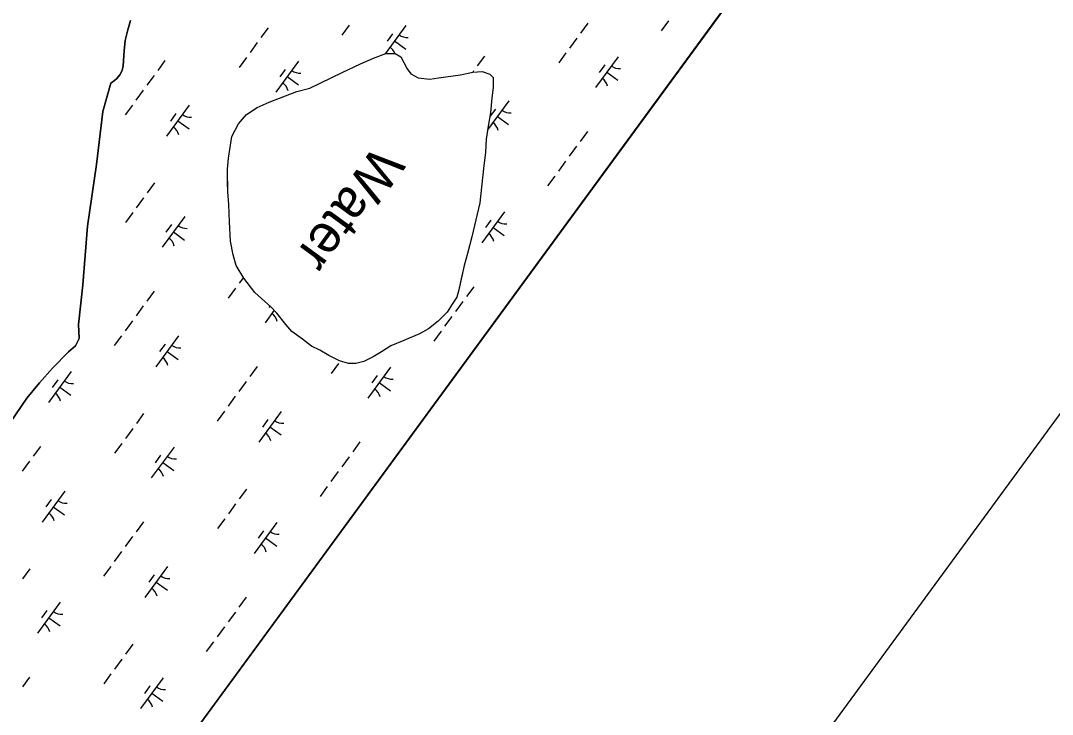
# Model space of a CAD drawing. Extents: x 3905714 to 3926767, y 183354 to 205755.
# Drawn here: x 3915741 to 3917087, y 185637 to 186542 of the extents above; entities that cross this region are included whole.
import ezdxf

# ---------------------------------------------------------------- set-up
doc = ezdxf.new("R2010")
doc.units = 0
for name, color, linetype in [('V-ANNO-SYMB', 7, 'Continuous'), ('V-GRID-FRAM', 7, 'Continuous'), ('V-RIVR-IDEN', 7, 'Continuous'), ('V-TOPO-SHOR', 7, 'Continuous'), ('V-WETL-SWMP', 7, 'Continuous')]:
    doc.layers.add(name, color=color, linetype=linetype)

msp = doc.modelspace()

# ---------------------------------------------------------------- linework, layer by layer
at = {"layer": 'V-ANNO-SYMB'}
msp.add_lwpolyline([(3916223.9, 204226), (3906447.8, 190882.4), (3915690.8, 184110.5), (3925467, 197454.1), (3916223.9, 204226)], dxfattribs=at)
at = {"layer": 'V-GRID-FRAM'}
msp.add_lwpolyline([(3924287.8, 196971.1), (3915521.4, 185005.6), (3909313.3, 189695.8), (3918205.9, 201877.9), (3924287.8, 196971.1)], dxfattribs=at)
at = {"layer": 'V-TOPO-SHOR'}
for points in [[(3915858.8, 186460.7), (3915863.5, 186464), (3915866.8, 186466.7), (3915870.8, 186471.3), (3915873.7, 186477.2), (3915875.2, 186483.1), (3915875.8, 186496), (3915876.3, 186502.8), (3915877.7, 186516), (3915881, 186530.3), (3915884.7, 186542.3)], [(3916261.4, 186133.8), (3916240.8, 186125.2), (3916224, 186118), (3916211.8, 186110.1), (3916200.8, 186103.5), (3916188.6, 186097.6), (3916178.3, 186094.9), (3916168.6, 186094.8), (3916156.9, 186098.6), (3916143.2, 186105.6), (3916131.5, 186112.6), (3916120.5, 186117.7), (3916108.8, 186126.7), (3916095.1, 186136.9), (3916087.2, 186145.9), (3916075.4, 186160.7), (3916067.6, 186169), (3916055.2, 186179.9), (3916046.7, 186187.6), (3916032.3, 186206.2), (3916022.5, 186223), (3916018.5, 186236.5), (3916015.1, 186254.6), (3916013.6, 186279.9), (3916012.7, 186302.5), (3916011.3, 186318.7), (3916011.2, 186331), (3916011, 186348.4), (3916012.2, 186362.7), (3916016.5, 186391.2), (3916025.4, 186407.4), (3916035.6, 186419.8), (3916049.8, 186429), (3916065.3, 186435.6), (3916086.5, 186444.2), (3916101.4, 186449.5), (3916118.2, 186454.2), (3916160.7, 186474.6), (3916184.5, 186485.8), (3916201.3, 186493.1), (3916217.4, 186499.1), (3916229.7, 186499.2), (3916236.9, 186494.7), (3916240.8, 186487.6), (3916245.4, 186479.3), (3916250, 186472.8), (3916259.8, 186467.7), (3916274.7, 186465.9), (3916286.3, 186467.3), (3916314.7, 186471.5), (3916330.9, 186474.8), (3916343.2, 186475.6), (3916352.9, 186472.4), (3916357.5, 186468), (3916357.6, 186455), (3916355.8, 186441.4), (3916354, 186422), (3916350.9, 186404.5), (3916348.5, 186387.6), (3916347.3, 186370.8), (3916344.9, 186349.4), (3916340.1, 186304.7), (3916329.5, 186260), (3916323.9, 186238.6), (3916319.5, 186223), (3916315.8, 186205.5), (3916312.7, 186191.2), (3916310.2, 186181.5), (3916303.8, 186172.4), (3916297.4, 186162), (3916285.9, 186150.2), (3916273, 186140.4), (3916261.4, 186133.8)], [(3915727.1, 186017), (3915749.2, 186049.8), (3915765.9, 186069.7), (3915782.9, 186088.9), (3915803.6, 186110.4), (3915812.7, 186118.1), (3915817.7, 186127.7), (3915816.8, 186146), (3915822.6, 186197.7), (3915828.5, 186274.3), (3915840.3, 186354.3), (3915848.5, 186423.6), (3915858.8, 186460.7)]]:
    msp.add_lwpolyline(points, dxfattribs=at)
at = {"layer": 'V-WETL-SWMP'}
for p, q in [((3915521.4, 185005.6), (3916758.4, 186694.1)), ((3915884.7, 186542.3), (3915881, 186530.3)), ((3916169.5, 186536.1), (3916160, 186523.2)), ((3916243.7, 186535.8), (3916216.5, 186498.8)), ((3916480.7, 186538.6), (3916471.3, 186525.7)), ((3916586.2, 186541.9), (3916576.7, 186529)), ((3915881, 186530.3), (3915877.7, 186516)), ((3916064.1, 186532.8), (3916054.6, 186519.9)), ((3916226.2, 186525), (3916219.1, 186515.3)), ((3915877.7, 186516), (3915876.3, 186502.8)), ((3916049.9, 186513.5), (3916040.4, 186500.6)), ((3916228.9, 186515.6), (3916243.4, 186505)), ((3916466.6, 186519.3), (3916457.1, 186506.4)), ((3915875.8, 186496), (3915875.2, 186483.1)), ((3915876.3, 186502.8), (3915875.8, 186496)), ((3916201.3, 186493.1), (3916217.4, 186499.1)), ((3916217.4, 186499.1), (3916229.7, 186499.2)), ((3916229.7, 186499.2), (3916236.9, 186494.7)), ((3916346.2, 186495.9), (3916336.8, 186483)), ((3916452.4, 186499.9), (3916442.9, 186487)), ((3915875.2, 186483.1), (3915873.7, 186477.2)), ((3915929.5, 186490.1), (3915920.1, 186477.2)), ((3916035.7, 186494.1), (3916026.2, 186481.2)), ((3916103.7, 186489.3), (3916074.2, 186448.9)), ((3916160.7, 186474.6), (3916184.5, 186485.8)), ((3916184.5, 186485.8), (3916201.3, 186493.1)), ((3916236.9, 186494.7), (3916245.4, 186479.3)), ((3916520.4, 186495.1), (3916490.8, 186454.8)), ((3916502.9, 186484.3), (3916495.8, 186474.6)), ((3915870.8, 186471.3), (3915866.8, 186466.7)), ((3915873.7, 186477.2), (3915870.8, 186471.3)), ((3915915.4, 186470.7), (3915905.9, 186457.8)), ((3916086.3, 186478.5), (3916079.2, 186468.8)), ((3916088.9, 186469.1), (3916103.5, 186458.5)), ((3916118.2, 186454.2), (3916160.7, 186474.6)), ((3916245.4, 186479.3), (3916250, 186472.8)), ((3916250, 186472.8), (3916259.8, 186467.7)), ((3916286.3, 186467.3), (3916314.7, 186471.5)), ((3916314.7, 186471.5), (3916330.9, 186474.8)), ((3916332, 186476.5), (3916330.8, 186474.8)), ((3916330.9, 186474.8), (3916343.2, 186475.6)), ((3916343.2, 186475.6), (3916352.9, 186472.4)), ((3916352.9, 186472.4), (3916357.5, 186468)), ((3916505.6, 186474.9), (3916520.1, 186464.3)), ((3915858.8, 186460.7), (3915848.5, 186423.6)), ((3915863.5, 186464), (3915858.8, 186460.7)), ((3915866.8, 186466.7), (3915863.5, 186464)), ((3916259.8, 186467.7), (3916274.7, 186465.9)), ((3916274.7, 186465.9), (3916286.3, 186467.3)), ((3916357.5, 186468), (3916357.6, 186455)), ((3915901.2, 186451.3), (3915891.7, 186438.4)), ((3916065.3, 186435.6), (3916086.5, 186444.2)), ((3916086.5, 186444.2), (3916101.4, 186449.5)), ((3916101.4, 186449.5), (3916118.2, 186454.2)), ((3916357.6, 186455), (3916355.8, 186441.4)), ((3915887, 186432), (3915877.5, 186419.1)), ((3915961.2, 186431.7), (3915931.6, 186391.3)), ((3916035.6, 186419.8), (3916049.8, 186429)), ((3916049.8, 186429), (3916065.3, 186435.6)), ((3916377.8, 186437.5), (3916350.2, 186399.8)), ((3916355.8, 186441.4), (3916354, 186422)), ((3915848.5, 186423.6), (3915840.3, 186354.3)), ((3915943.7, 186420.9), (3915936.6, 186411.2)), ((3916025.4, 186407.4), (3916035.6, 186419.8)), ((3916354, 186422), (3916350.9, 186404.5)), ((3916360.4, 186426.7), (3916353.3, 186417)), ((3916363.1, 186417.3), (3916377.6, 186406.7)), ((3915946.4, 186411.5), (3915960.9, 186400.8)), ((3916016.5, 186391.2), (3916025.4, 186407.4)), ((3916350.9, 186404.5), (3916348.5, 186387.6)), ((3916012.2, 186362.7), (3916016.5, 186391.2)), ((3916480.4, 186397.6), (3916470.9, 186384.7)), ((3916348.5, 186387.6), (3916347.3, 186370.8)), ((3916466.2, 186378.2), (3916456.7, 186365.3)), ((3916011, 186348.4), (3916012.2, 186362.7)), ((3916347.3, 186370.8), (3916344.9, 186349.4)), ((3915840.3, 186354.3), (3915828.5, 186274.3)), ((3916011.3, 186318.7), (3916011, 186348.4)), ((3916344.9, 186349.4), (3916340.1, 186304.7)), ((3916452, 186358.9), (3916442.6, 186346)), ((3916437.8, 186339.5), (3916428.4, 186326.6)), ((3915915.8, 186330.4), (3915906.3, 186317.5)), ((3915901.6, 186311), (3915892.1, 186298.1)), ((3916012.7, 186302.5), (3916011.3, 186318.7)), ((3916013.6, 186279.9), (3916012.7, 186302.5)), ((3916340.1, 186304.7), (3916329.5, 186260)), ((3915887.4, 186291.7), (3915877.9, 186278.8)), ((3915955.4, 186286.8), (3915925.8, 186246.5)), ((3916372.1, 186292.7), (3916342.5, 186252.3)), ((3916354.6, 186281.9), (3916347.5, 186272.2)), ((3915828.5, 186274.3), (3915822.6, 186197.7)), ((3915937.9, 186276.1), (3915930.8, 186266.4)), ((3916015.1, 186254.6), (3916013.6, 186279.9)), ((3916357.3, 186272.5), (3916371.8, 186261.8)), ((3915940.6, 186266.7), (3915955.1, 186256)), ((3916018.5, 186236.5), (3916015.1, 186254.6)), ((3916329.5, 186260), (3916323.9, 186238.6)), ((3916022.5, 186223), (3916018.5, 186236.5)), ((3916323.9, 186238.6), (3916319.5, 186223)), ((3916032.3, 186206.2), (3916022.5, 186223)), ((3916319.5, 186223), (3916312.7, 186191.2)), ((3916031.7, 186207.2), (3916026.3, 186199.8)), ((3916046.7, 186187.6), (3916032.3, 186206.2)), ((3915822.6, 186197.7), (3915816.8, 186146)), ((3915915.4, 186189.3), (3915905.9, 186176.4)), ((3916021.6, 186193.4), (3916012.1, 186180.4)), ((3916055.2, 186179.9), (3916046.7, 186187.6)), ((3916312.7, 186191.2), (3916310.2, 186181.5)), ((3916332.1, 186195.1), (3916322.6, 186182.2)), ((3916067.6, 186169), (3916055.2, 186179.9)), ((3916310.2, 186181.5), (3916303.8, 186172.4)), ((3916317.9, 186175.8), (3916308.4, 186162.9)), ((3915901.2, 186170), (3915891.8, 186157)), ((3916071.9, 186164.4), (3916060, 186148.2)), ((3916066.5, 186170), (3916065, 186168.1)), ((3916075.4, 186160.7), (3916067.6, 186169)), ((3916087.2, 186145.9), (3916075.4, 186160.7)), ((3916297.4, 186162), (3916285.9, 186150.2)), ((3916303.8, 186172.4), (3916297.4, 186162)), ((3915816.8, 186146), (3915817.7, 186127.7)), ((3915887, 186150.6), (3915877.6, 186137.7)), ((3916095.1, 186136.9), (3916087.2, 186145.9)), ((3916285.9, 186150.2), (3916273, 186140.4)), ((3916303.7, 186156.4), (3916294.2, 186143.5)), ((3916108.8, 186126.7), (3916095.1, 186136.9)), ((3916261.4, 186133.8), (3916240.8, 186125.2)), ((3916273, 186140.4), (3916261.4, 186133.8)), ((3916289.5, 186137.1), (3916280.1, 186124.2)), ((3915817.7, 186127.7), (3915812.7, 186118.1)), ((3915872.8, 186131.2), (3915863.4, 186118.3)), ((3915947, 186130.9), (3915917.5, 186090.6)), ((3915929.6, 186120.1), (3915922.5, 186110.5)), ((3916120.5, 186117.7), (3916108.8, 186126.7)), ((3916240.8, 186125.2), (3916224, 186118)), ((3915803.6, 186110.4), (3915782.9, 186088.9)), ((3915812.7, 186118.1), (3915803.6, 186110.4)), ((3915932.3, 186110.7), (3915946.8, 186100.1)), ((3916131.5, 186112.6), (3916120.5, 186117.7)), ((3916143.2, 186105.6), (3916131.5, 186112.6)), ((3916156.9, 186098.6), (3916143.2, 186105.6)), ((3916211.8, 186110.1), (3916200.8, 186103.5)), ((3916224, 186118), (3916211.8, 186110.1)), ((3916155.7, 186095), (3916146.3, 186082.1)), ((3916168.6, 186094.8), (3916156.9, 186098.6)), ((3916178.3, 186094.9), (3916168.6, 186094.8)), ((3916188.6, 186097.6), (3916178.3, 186094.9)), ((3916200.8, 186103.5), (3916188.6, 186097.6)), ((3915782.9, 186088.9), (3915765.9, 186069.7)), ((3915807.1, 186084.4), (3915777.5, 186044.1)), ((3916049.6, 186091), (3916040.1, 186078.1)), ((3916223.8, 186090.2), (3916194.2, 186049.9)), ((3916206.3, 186079.5), (3916199.2, 186069.8)), ((3915765.9, 186069.7), (3915749.2, 186049.8)), ((3915789.6, 186073.6), (3915782.5, 186063.9)), ((3916035.4, 186071.6), (3916025.9, 186058.7)), ((3916209, 186070.1), (3916223.5, 186059.4)), ((3915792.3, 186064.2), (3915806.8, 186053.6)), ((3916021.2, 186052.3), (3916011.8, 186039.4)), ((3915749.2, 186049.8), (3915727.1, 186017)), ((3915901.6, 186029.6), (3915892.2, 186016.7)), ((3916007, 186032.9), (3915997.6, 186020)), ((3916081.2, 186032.6), (3916051.7, 185992.3)), ((3916063.8, 186021.8), (3916056.7, 186012.2)), ((3916066.4, 186012.4), (3916081, 186001.8)), ((3915887.4, 186010.3), (3915878, 185997.4)), ((3915767.1, 185986.9), (3915757.6, 185974)), ((3915873.2, 185990.9), (3915863.8, 185978)), ((3915941.3, 185986.1), (3915911.7, 185945.8)), ((3916183.8, 185992.7), (3916174.3, 185979.8)), ((3915923.8, 185975.3), (3915916.7, 185965.6)), ((3916169.6, 185973.3), (3916160.1, 185960.4)), ((3915752.9, 185967.5), (3915743.4, 185954.6)), ((3915926.5, 185965.9), (3915941, 185955.3)), ((3916155.4, 185954), (3916145.9, 185941.1)), ((3916035.8, 185931.3), (3916026.3, 185918.4)), ((3916141.2, 185934.6), (3916131.8, 185921.7)), ((3915798.7, 185928.5), (3915769.2, 185888.1)), ((3915781.3, 185917.7), (3915774.2, 185908)), ((3915783.9, 185908.3), (3915798.5, 185897.7)), ((3916021.6, 185912), (3916012.2, 185899.1)), ((3916007.4, 185892.6), (3915998, 185879.7)), ((3915901.3, 185888.6), (3915891.8, 185875.7)), ((3916075.4, 185887.8), (3916045.9, 185847.4)), ((3916058, 185877), (3916050.9, 185867.3)), ((3915887.1, 185869.2), (3915877.6, 185856.3)), ((3916060.7, 185867.6), (3916075.2, 185857)), ((3915872.9, 185849.9), (3915863.4, 185836.9)), ((3915753.3, 185827.2), (3915743.8, 185814.3)), ((3915858.7, 185830.5), (3915849.3, 185817.6)), ((3915932.9, 185830.2), (3915903.3, 185789.8)), ((3915915.4, 185819.4), (3915908.4, 185809.7)), ((3915918.1, 185810), (3915932.6, 185799.4)), ((3915792.9, 185783.6), (3915763.4, 185743.3)), ((3916035.4, 185790.3), (3916026, 185777.4)), ((3915775.5, 185772.9), (3915768.4, 185763.2)), ((3916021.3, 185770.9), (3916011.8, 185758)), ((3915778.2, 185763.5), (3915792.7, 185752.8)), ((3916007.1, 185751.5), (3915997.6, 185738.6)), ((3915887.5, 185728.9), (3915878, 185716)), ((3915992.9, 185732.2), (3915983.4, 185719.3)), ((3915873.3, 185709.5), (3915863.8, 185696.6)), ((3915859.1, 185690.2), (3915849.7, 185677.3)), ((3915753, 185686.1), (3915743.5, 185673.2)), ((3915927.1, 185685.3), (3915897.6, 185645)), ((3915909.7, 185674.6), (3915902.6, 185664.9)), ((3915912.3, 185665.2), (3915926.9, 185654.5))]:
    msp.add_line(p, q, dxfattribs=at)
for centre, start, end in [((3916245.4, 186537.8), 233, 274.5436), ((3916212.8, 186493.2), 19.8803, 54.5436), ((3916522.1, 186497.1), 233, 274.5436), ((3916105.4, 186491.2), 233, 274.5436), ((3916072.8, 186446.7), 13, 54.5436), ((3916489.5, 186452.5), 13, 54.5436), ((3915962.9, 186433.6), 233, 274.5436), ((3916379.6, 186439.4), 233, 274.5436), ((3915930.3, 186389.1), 13, 54.5436), ((3916346.9, 186394.9), 13, 54.5436), ((3916373.8, 186294.6), 233, 274.5436), ((3915957.1, 186288.8), 233, 274.5436), ((3915924.5, 186244.2), 13, 54.5436), ((3916341.2, 186250.1), 13, 54.5436), ((3916058.7, 186145.9), 13, 54.5436), ((3915948.8, 186132.9), 233, 274.5436), ((3915916.1, 186088.3), 13, 54.5436), ((3915808.8, 186086.4), 233, 274.5436), ((3916225.5, 186092.2), 233, 274.5436), ((3915776.2, 186041.8), 13, 54.5436), ((3916192.8, 186047.6), 13, 54.5436), ((3916083, 186034.6), 233, 274.5436), ((3916050.3, 185990), 13, 54.5436), ((3915943, 185988.1), 233, 274.5436), ((3915910.3, 185943.5), 13, 54.5436), ((3915800.5, 185930.4), 233, 274.5436), ((3915767.8, 185885.9), 13, 54.5436), ((3916077.2, 185889.8), 233, 274.5436), ((3916044.5, 185845.2), 13, 54.5436), ((3915934.6, 185832.1), 233, 274.5436), ((3915902, 185787.6), 13, 54.5436), ((3915794.7, 185785.6), 233, 274.5436), ((3915762, 185741.1), 13, 54.5436), ((3915928.9, 185687.3), 233, 274.5436), ((3915896.2, 185642.8), 13, 54.5436)]:
    msp.add_arc(centre, 17.6, start, end, dxfattribs=at)

# ---------------------------------------------------------------- texts
at = {"layer": 'V-RIVR-IDEN'}
msp.add_text('Water', height=50, rotation=233.8714, dxfattribs=at).set_placement((3916203.9, 186381.5))

doc.saveas('drawing.dxf')
